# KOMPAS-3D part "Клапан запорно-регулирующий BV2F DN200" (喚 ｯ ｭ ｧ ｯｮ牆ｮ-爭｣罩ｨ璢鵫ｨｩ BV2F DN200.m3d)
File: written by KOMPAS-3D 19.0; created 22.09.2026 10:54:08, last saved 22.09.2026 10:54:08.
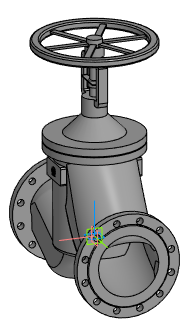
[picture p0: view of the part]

Document properties: Автор: Энергия; Полное имя файла: Z:\3.Личные\sachek\Dendor\_3D для проектировщиков\5.7 Клапан запорно-регулирующий BV2F\BV2F_STP\Клапан запорно-регулирующий BV2F DN200.m3d

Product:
- Part/product: Клапан запорно-регулирующий BV2F DN200

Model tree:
1. Операция без истории:1  (labels: Клапан запорно-регулирующий BV2F DN200)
